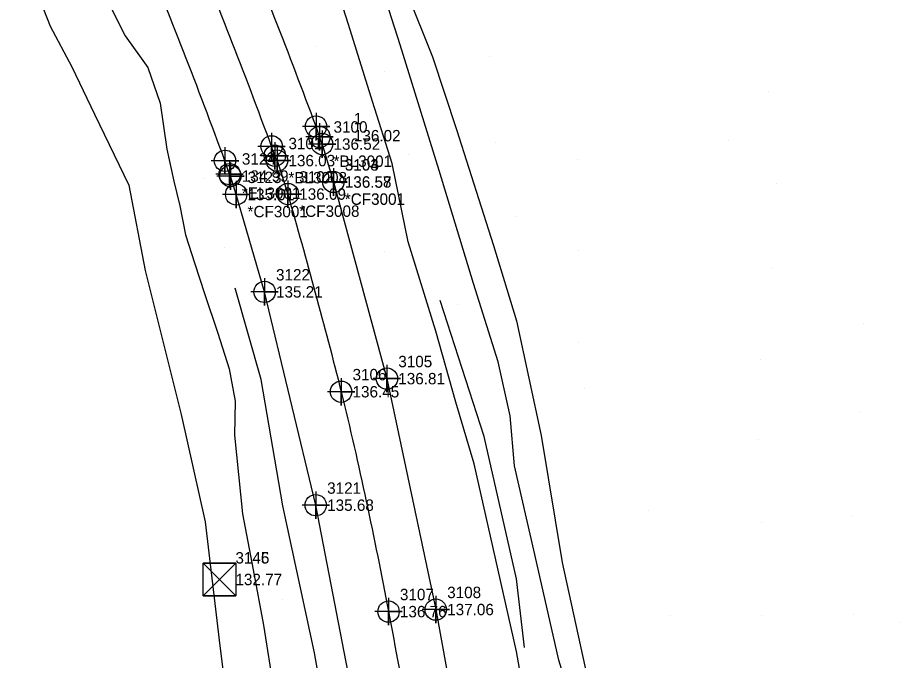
# Model space of a CAD drawing. Extents: x 2312183 to 2312663, y 819676 to 820746.
# Drawn here: x 2312371.9 to 2312565.2, y 820324.9 to 820465.8 of the extents above; entities that cross this region are included whole.
import ezdxf

# ---------------------------------------------------------------- set-up
doc = ezdxf.new("R2010")
doc.units = 0
for name, color, linetype in [('CTL Bench Mark CELL', 7, 'Continuous'), ('CTL Bench Mark Cogo Elevation', 7, 'Continuous'), ('CTL Bench Mark Cogo Number', 7, 'Continuous'), ('CTL Supplemental Horizontal and Vertical Cogo Elevation', 7, 'Continuous'), ('CTL Supplemental Horizontal and Vertical Cogo Number', 7, 'Continuous'), ('Exist DTM Crownline', 7, 'Continuous'), ('Exist DTM Crownline Cogo Comment', 7, 'Continuous'), ('Exist DTM Crownline Cogo Elevation', 7, 'Continuous'), ('Exist DTM Crownline Cogo Number', 7, 'Continuous'), ('Exist DTM Crownline Cogo Point CELL', 7, 'Continuous'), ('Exist Roads EOP', 7, 'Continuous'), ('Exist Roads EOP Cogo Comment', 7, 'Continuous'), ('Exist Roads EOP Cogo Elevation', 7, 'Continuous'), ('Exist Roads EOP Cogo Number', 7, 'Continuous'), ('Exist Roads EOP Cogo Point CELL', 7, 'Continuous'), ('PH Exist DTM Breakline', 7, 'Continuous'), ('PH Exist DTM Point', 7, 'Continuous')]:
    doc.layers.add(name, color=color, linetype=linetype)

msp = doc.modelspace()

# ---------------------------------------------------------------- linework, layer by layer
at = {"layer": 'CTL Bench Mark CELL'}
msp.add_line((2312416.1, 820342.6), (2312416.1, 820342.6), dxfattribs=at)
msp.add_line((2312416.1, 820342.6), (2312416.1, 820342.6), dxfattribs=at)
msp.add_line((2312416.1, 820342.6), (2312416.1, 820342.6), dxfattribs=at)
msp.add_line((2312416.1, 820342.6), (2312416.1, 820342.6), dxfattribs=at)
msp.add_lwpolyline([(2312412.5, 820346.19), (2312419.69, 820346.19), (2312419.69, 820339), (2312412.5, 820339)], close=True, dxfattribs=at)
msp.add_lwpolyline([(2312412.5, 820346.19), (2312419.69, 820346.19), (2312419.69, 820339), (2312412.5, 820339)], close=True, dxfattribs=at)
msp.add_lwpolyline([(2312412.5, 820346.19), (2312419.69, 820346.19), (2312419.69, 820339), (2312412.5, 820339)], close=True, dxfattribs=at)
msp.add_lwpolyline([(2312412.5, 820346.19), (2312419.69, 820346.19), (2312419.69, 820339), (2312412.5, 820339)], close=True, dxfattribs=at)
for points in [[(2312419.69, 820346.19), (2312412.5, 820339), (2312416.1, 820342.6), (2312419.69, 820339), (2312412.5, 820346.19)], [(2312416.1, 820342.6), (2312419.69, 820346.19), (2312412.5, 820346.19), (2312416.1, 820342.6)], [(2312419.69, 820346.19), (2312412.5, 820339), (2312416.1, 820342.59), (2312419.69, 820339), (2312412.5, 820346.19)], [(2312416.1, 820342.59), (2312419.69, 820346.19), (2312412.5, 820346.19), (2312416.1, 820342.59)], [(2312419.69, 820346.19), (2312412.5, 820339), (2312416.1, 820342.59), (2312419.69, 820339), (2312412.5, 820346.19)], [(2312416.1, 820342.59), (2312419.69, 820346.19), (2312412.5, 820346.19), (2312416.1, 820342.59)], [(2312419.69, 820346.19), (2312412.5, 820339), (2312416.1, 820342.6), (2312419.69, 820339), (2312412.5, 820346.19)], [(2312416.1, 820342.6), (2312419.69, 820346.19), (2312412.5, 820346.19), (2312416.1, 820342.6)], [(2312416.1, 820342.6), (2312412.5, 820339), (2312419.69, 820339), (2312416.1, 820342.6)], [(2312416.1, 820342.6), (2312412.5, 820339), (2312419.69, 820339), (2312416.1, 820342.6)], [(2312416.1, 820342.59), (2312412.5, 820339), (2312419.69, 820339), (2312416.1, 820342.59)], [(2312416.1, 820342.59), (2312412.5, 820339), (2312419.69, 820339), (2312416.1, 820342.59)]]:
    msp.add_lwpolyline(points, dxfattribs=at)
at = {"layer": 'Exist DTM Crownline'}
for p, q in [((2312428.23, 820435.5), (2312427.52, 820437.54)), ((2312428.71, 820434.43), (2312431.08, 820427.09))]:
    msp.add_line(p, q, dxfattribs=at)
msp.add_lwpolyline([(2312428.71, 820434.43), (2312428.23, 820435.5)], dxfattribs=at)
for points in [[(2312427.52, 820437.54), (2312408.57, 820485.39), (2312385.43, 820531.09), (2312358.13, 820575.86), (2312333.19, 820609.81), (2312297.49, 820652.78)], [(2312431.08, 820427.09), (2312442.75, 820383.76), (2312453.13, 820335.56), (2312461.58, 820287.26), (2312468.33, 820241.58), (2312470.08, 820228.19)]]:
    msp.add_spline(points, degree=3, dxfattribs=at)
at = {"layer": 'Exist DTM Crownline Cogo Point CELL'}
for points in [[(2312427.52, 820440.54), (2312427.52, 820434.54), (2312427.52, 820437.54), (2312430.52, 820437.54), (2312424.52, 820437.54)], [(2312428.23, 820438.5), (2312428.23, 820432.5), (2312428.23, 820435.5), (2312431.23, 820435.5), (2312425.23, 820435.5)], [(2312428.71, 820437.43), (2312428.71, 820431.43), (2312428.71, 820434.43), (2312431.71, 820434.43), (2312425.71, 820434.43)], [(2312428.71, 820437.43), (2312428.71, 820431.43), (2312428.71, 820434.43), (2312431.71, 820434.43), (2312425.71, 820434.43)], [(2312431.08, 820430.09), (2312431.08, 820424.09), (2312431.08, 820427.09), (2312434.08, 820427.09), (2312428.08, 820427.09)], [(2312431.08, 820430.09), (2312431.08, 820424.09), (2312431.08, 820427.09), (2312434.08, 820427.09), (2312428.08, 820427.09)], [(2312442.75, 820386.76), (2312442.75, 820380.76), (2312442.75, 820383.76), (2312445.75, 820383.76), (2312439.75, 820383.76)], [(2312442.75, 820386.76), (2312442.75, 820380.76), (2312442.75, 820383.76), (2312445.75, 820383.76), (2312439.75, 820383.76)], [(2312453.13, 820338.56), (2312453.13, 820332.56), (2312453.13, 820335.56), (2312456.13, 820335.56), (2312450.13, 820335.56)], [(2312453.13, 820338.56), (2312453.13, 820332.56), (2312453.13, 820335.56), (2312456.13, 820335.56), (2312450.13, 820335.56)]]:
    msp.add_lwpolyline(points, dxfattribs=at)
for centre in [(2312427.52, 820437.54), (2312428.23, 820435.5), (2312428.71, 820434.43), (2312428.71, 820434.43), (2312431.08, 820427.09), (2312431.08, 820427.09), (2312442.75, 820383.76), (2312442.75, 820383.76), (2312453.13, 820335.56), (2312453.13, 820335.56)]:
    msp.add_circle(centre, 2.34, dxfattribs=at)
at = {"layer": 'Exist Roads EOP'}
for p, q in [((2312438.01, 820439.61), (2312437.27, 820441.9)), ((2312438.59, 820438.05), (2312441.06, 820429.72)), ((2312418.31, 820431.45), (2312417.31, 820434.38)), ((2312419.76, 820427), (2312418.51, 820431.04)), ((2312441.06, 820429.72), (2312441.05, 820429.75))]:
    msp.add_line(p, q, dxfattribs=at)
for points in [[(2312438.59, 820438.05), (2312438.01, 820439.61)], [(2312418.51, 820431.04), (2312418.31, 820431.45)], [(2312441.05, 820429.75), (2312452.77, 820386.63), (2312463.48, 820336.01), (2312472.02, 820288.73), (2312479.07, 820242.19), (2312480.59, 820230.27)], [(2312459.22, 820221.98), (2312453.84, 820264.93), (2312446.37, 820311.63), (2312437.19, 820358.89), (2312425.99, 820405.65), (2312419.76, 820427)]]:
    msp.add_lwpolyline(points, dxfattribs=at)
for points in [[(2312437.27, 820441.9), (2312418.59, 820489.03), (2312394.67, 820536.19), (2312367.38, 820580.54)], [(2312417.31, 820434.38), (2312398.47, 820481.99), (2312376.08, 820525.96), (2312349.36, 820569.45)]]:
    msp.add_spline(points, degree=3, dxfattribs=at)
at = {"layer": 'Exist Roads EOP Cogo Point CELL'}
for points in [[(2312437.27, 820444.9), (2312437.27, 820438.9), (2312437.27, 820441.9), (2312440.27, 820441.9), (2312434.27, 820441.9)], [(2312438.01, 820442.61), (2312438.01, 820436.61), (2312438.01, 820439.61), (2312441.01, 820439.61), (2312435.01, 820439.61)], [(2312438.59, 820441.05), (2312438.59, 820435.05), (2312438.59, 820438.05), (2312441.59, 820438.05), (2312435.59, 820438.05)], [(2312438.59, 820441.05), (2312438.59, 820435.05), (2312438.59, 820438.05), (2312441.59, 820438.05), (2312435.59, 820438.05)], [(2312438.59, 820441.05), (2312438.59, 820435.05), (2312438.59, 820438.05), (2312441.59, 820438.05), (2312435.59, 820438.05)], [(2312417.31, 820437.38), (2312417.31, 820431.38), (2312417.31, 820434.38), (2312420.31, 820434.38), (2312414.31, 820434.38)], [(2312418.31, 820434.45), (2312418.31, 820428.45), (2312418.31, 820431.45), (2312421.31, 820431.45), (2312415.31, 820431.45)], [(2312418.51, 820434.04), (2312418.51, 820428.04), (2312418.51, 820431.04), (2312421.51, 820431.04), (2312415.51, 820431.04)], [(2312418.51, 820434.04), (2312418.51, 820428.04), (2312418.51, 820431.04), (2312421.51, 820431.04), (2312415.51, 820431.04)], [(2312418.51, 820434.04), (2312418.51, 820428.04), (2312418.51, 820431.04), (2312421.51, 820431.04), (2312415.51, 820431.04)], [(2312441.05, 820432.75), (2312441.05, 820426.75), (2312441.05, 820429.75), (2312444.05, 820429.75), (2312438.05, 820429.75)], [(2312441.05, 820432.75), (2312441.05, 820426.75), (2312441.05, 820429.75), (2312444.05, 820429.75), (2312438.05, 820429.75)], [(2312441.05, 820432.75), (2312441.05, 820426.75), (2312441.05, 820429.75), (2312444.05, 820429.75), (2312438.05, 820429.75)], [(2312441.06, 820432.72), (2312441.06, 820426.72), (2312441.06, 820429.72), (2312444.06, 820429.72), (2312438.06, 820429.72)], [(2312441.06, 820432.72), (2312441.06, 820426.72), (2312441.06, 820429.72), (2312444.06, 820429.72), (2312438.06, 820429.72)], [(2312441.06, 820432.72), (2312441.06, 820426.72), (2312441.06, 820429.72), (2312444.06, 820429.72), (2312438.06, 820429.72)], [(2312419.76, 820430), (2312419.76, 820424), (2312419.76, 820427), (2312422.76, 820427), (2312416.76, 820427)], [(2312419.76, 820430), (2312419.76, 820424), (2312419.76, 820427), (2312422.76, 820427), (2312416.76, 820427)], [(2312419.76, 820430), (2312419.76, 820424), (2312419.76, 820427), (2312422.76, 820427), (2312416.76, 820427)], [(2312425.99, 820408.65), (2312425.99, 820402.65), (2312425.99, 820405.65), (2312428.99, 820405.65), (2312422.99, 820405.65)], [(2312425.99, 820408.65), (2312425.99, 820402.65), (2312425.99, 820405.65), (2312428.99, 820405.65), (2312422.99, 820405.65)], [(2312425.99, 820408.65), (2312425.99, 820402.65), (2312425.99, 820405.65), (2312428.99, 820405.65), (2312422.99, 820405.65)], [(2312452.77, 820389.63), (2312452.77, 820383.63), (2312452.77, 820386.63), (2312455.77, 820386.63), (2312449.77, 820386.63)], [(2312452.77, 820389.63), (2312452.77, 820383.63), (2312452.77, 820386.63), (2312455.77, 820386.63), (2312449.77, 820386.63)], [(2312437.19, 820361.89), (2312437.19, 820355.89), (2312437.19, 820358.89), (2312440.19, 820358.89), (2312434.19, 820358.89)], [(2312437.19, 820361.89), (2312437.19, 820355.89), (2312437.19, 820358.89), (2312440.19, 820358.89), (2312434.19, 820358.89)], [(2312437.19, 820361.89), (2312437.19, 820355.89), (2312437.19, 820358.89), (2312440.19, 820358.89), (2312434.19, 820358.89)], [(2312463.48, 820339.01), (2312463.48, 820333.01), (2312463.48, 820336.01), (2312466.48, 820336.01), (2312460.48, 820336.01)], [(2312463.48, 820339.01), (2312463.48, 820333.01), (2312463.48, 820336.01), (2312466.48, 820336.01), (2312460.48, 820336.01)], [(2312463.48, 820339.01), (2312463.48, 820333.01), (2312463.48, 820336.01), (2312466.48, 820336.01), (2312460.48, 820336.01)]]:
    msp.add_lwpolyline(points, dxfattribs=at)
for centre in [(2312437.27, 820441.9), (2312438.01, 820439.61), (2312438.59, 820438.05), (2312438.59, 820438.05), (2312438.59, 820438.05), (2312417.31, 820434.38), (2312418.31, 820431.45), (2312418.51, 820431.04), (2312418.51, 820431.04), (2312418.51, 820431.04), (2312441.05, 820429.75), (2312441.05, 820429.75), (2312441.05, 820429.75), (2312441.06, 820429.72), (2312441.06, 820429.72), (2312441.06, 820429.72), (2312419.76, 820427), (2312419.76, 820427), (2312419.76, 820427), (2312425.99, 820405.65), (2312425.99, 820405.65), (2312425.99, 820405.65), (2312452.77, 820386.63), (2312452.77, 820386.63), (2312437.19, 820358.89), (2312437.19, 820358.89), (2312437.19, 820358.89), (2312463.48, 820336.01), (2312463.48, 820336.01), (2312463.48, 820336.01)]:
    msp.add_circle(centre, 2.34, dxfattribs=at)
at = {"layer": 'PH Exist DTM Breakline'}
for points in [[(2312477.16, 820390.3), (2312471.74, 820407.46), (2312464.23, 820432.23), (2312455.71, 820459.83), (2312449.64, 820478.79), (2312444.49, 820489.71), (2312438.95, 820498.67), (2312430.86, 820508.29), (2312423.23, 820518.79), (2312417.85, 820527.39), (2312410.24, 820542.77), (2312403.93, 820554.09), (2312394.96, 820567.28), (2312386.75, 820580.38), (2312374.65, 820596.09)], [(2312496.98, 820211.89), (2312494.87, 820230.31), (2312493.52, 820258.27), (2312489.57, 820280.07), (2312484.22, 820309.45), (2312481.15, 820326.81), (2312475.44, 820352.08), (2312471.91, 820367.92), (2312467.91, 820381.46), (2312463.46, 820397.01), (2312457.42, 820416.6), (2312453.92, 820433.79), (2312449.6, 820447.37), (2312444.37, 820464.27), (2312438.97, 820481.2), (2312434.26, 820489.97), (2312425.05, 820503.84), (2312418.26, 820512.36), (2312411.06, 820524.77), (2312404.5, 820537.31), (2312396.07, 820550.91), (2312386.97, 820563.26), (2312378.04, 820577.42), (2312367.52, 820592.37)], [(2312323.19, 820565.09), (2312341.16, 820534.9), (2312360.25, 820506.1), (2312372.41, 820480.89), (2312379, 820463.92), (2312383.77, 820454.95), (2312388.75, 820444.62), (2312396.25, 820429.05), (2312399.86, 820410.35), (2312407.68, 820378.77), (2312412.99, 820355.24), (2312416.17, 820328.02), (2312417.67, 820316.52), (2312422.05, 820275.27)], [(2312391.16, 820470.38), (2312395.48, 820461.78), (2312400.38, 820454.86), (2312403.14, 820447.03), (2312404.56, 820436.92), (2312406.09, 820429.89), (2312407.4, 820424.49), (2312408.69, 820418.16), (2312410.67, 820411.79), (2312412.86, 820405.28), (2312415.75, 820396.58), (2312418.23, 820388.76), (2312419.52, 820381.7), (2312419.42, 820374.21), (2312421.17, 820356.99), (2312423.46, 820344.75), (2312425.78, 820332.58), (2312428.01, 820318.28), (2312429.7, 820304.94), (2312430.08, 820283.91), (2312430.55, 820272.02), (2312432.01, 820256.8), (2312435.53, 820209.02), (2312436.94, 820204.43)], [(2312457.31, 820470.89), (2312462.78, 820457.19), (2312468.03, 820441.23), (2312476.14, 820415.82), (2312481.16, 820399.28), (2312486.57, 820374.14), (2312491.18, 820346.35), (2312497.16, 820318.89), (2312506.05, 820290.48), (2312509.86, 820279.25), (2312517.03, 820263.97), (2312521.4, 820250.94), (2312524.81, 820240.42), (2312528.04, 820230.48), (2312531.48, 820219.81)], [(2312455.99, 820200.73), (2312449.75, 820231.37), (2312446.75, 820268.11), (2312440.9, 820303.62), (2312436.92, 820326.5), (2312429.99, 820358.74), (2312425.22, 820386.43), (2312419.51, 820406.46)], [(2312482.95, 820327.66), (2312481.14, 820342.74), (2312474.11, 820373.94), (2312464.42, 820403.76)], [(2312502.61, 820280.69), (2312499.1, 820296.81), (2312490.43, 820324.88), (2312485.21, 820348.1), (2312480.72, 820367.48), (2312479.81, 820378.49), (2312477.16, 820390.3)]]:
    msp.add_lwpolyline(points, dxfattribs=at)
at = {"layer": 'PH Exist DTM Point'}
for p, q in [((2312437.25, 820459.49), (2312437.25, 820459.49)), ((2312475.19, 820457.14), (2312475.19, 820457.14)), ((2312452.19, 820453.89), (2312452.19, 820453.89)), ((2312536.4, 820449.58), (2312536.4, 820449.58)), ((2312527.64, 820438.76), (2312527.64, 820438.76)), ((2312476.61, 820438.32), (2312476.61, 820438.32)), ((2312457.47, 820435.71), (2312457.47, 820435.71)), ((2312494.63, 820434.61), (2312494.63, 820434.61)), ((2312412.64, 820430.61), (2312412.64, 820430.61)), ((2312538.09, 820429.49), (2312538.09, 820429.49)), ((2312481.27, 820422.12), (2312481.27, 820422.12)), ((2312417.2, 820415.35), (2312417.2, 820415.35)), ((2312452.32, 820414.58), (2312452.32, 820414.58)), ((2312494.79, 820414.66), (2312494.79, 820414.66)), ((2312537.34, 820410.69), (2312537.34, 820410.69)), ((2312468.25, 820402.81), (2312468.25, 820402.81)), ((2312557.21, 820398.72), (2312557.21, 820398.72)), ((2312494.69, 820394.63), (2312494.69, 820394.63)), ((2312534.52, 820390.76), (2312534.52, 820390.76)), ((2312496.03, 820384.45), (2312496.03, 820384.45)), ((2312556.61, 820379.12), (2312556.61, 820379.12)), ((2312534.27, 820373.25), (2312534.27, 820373.25)), ((2312510.05, 820357.63), (2312510.05, 820357.63)), ((2312554.56, 820356.36), (2312554.56, 820356.36)), ((2312534.72, 820355.14), (2312534.72, 820355.14)), ((2312429.98, 820338.25), (2312429.98, 820338.25)), ((2312474.46, 820335.27), (2312474.46, 820335.27)), ((2312514.87, 820334.69), (2312514.87, 820334.69)), ((2312534.77, 820334.66), (2312534.77, 820334.66)), ((2312555.08, 820334.85), (2312555.08, 820334.85)), ((2312565.24, 820333.17), (2312565.24, 820333.17))]:
    msp.add_line(p, q, dxfattribs=at)

# ---------------------------------------------------------------- texts
at = {"layer": 'CTL Bench Mark Cogo Elevation'}
msp.add_text('132.77', height=2.5, dxfattribs=at).set_placement((2312419.6, 820341.35))
msp.add_text('132.77', height=2.5, dxfattribs=at).set_placement((2312419.6, 820341.35))
at = {"layer": 'CTL Bench Mark Cogo Number'}
for s in ['3145', '3146']:
    msp.add_text(s, height=2.5, dxfattribs=at).set_placement((2312419.6, 820346.1))
at = {"layer": 'CTL Supplemental Horizontal and Vertical Cogo Elevation'}
msp.add_text('136.02', height=2.5, dxfattribs=at).set_placement((2312445.55, 820438.64))
at = {"layer": 'CTL Supplemental Horizontal and Vertical Cogo Number'}
msp.add_text('1', height=2.5, dxfattribs=at).set_placement((2312445.55, 820442.39))
at = {"layer": 'Exist DTM Crownline Cogo Comment'}
for s, p in [('*BL3008', (2312431.21, 820429.43)), ('*CF3008', (2312433.58, 820422.09))]:
    msp.add_text(s, height=2.5, dxfattribs=at).set_placement(p)
at = {"layer": 'Exist DTM Crownline Cogo Elevation'}
for s, p in [('136.03', (2312431.21, 820433.18)), ('136.09', (2312433.58, 820425.84)), ('136.45', (2312445.25, 820382.51)), ('136.76', (2312455.63, 820334.31))]:
    msp.add_text(s, height=2.5, dxfattribs=at).set_placement(p)
at = {"layer": 'Exist DTM Crownline Cogo Number'}
for s, p in [('3101', (2312431.21, 820436.93)), ('3102', (2312433.58, 820429.59)), ('3106', (2312445.25, 820386.26)), ('3107', (2312455.63, 820338.06))]:
    msp.add_text(s, height=2.5, dxfattribs=at).set_placement(p)
at = {"layer": 'Exist Roads EOP Cogo Comment'}
for s, p in [('*BL3001', (2312441.09, 820433.05)), ('*EL3001', (2312421.01, 820426.04)), ('*CF3001', (2312443.55, 820424.75)), ('*CF3001', (2312443.56, 820424.72)), ('*CF3001', (2312422.26, 820422))]:
    msp.add_text(s, height=2.5, dxfattribs=at).set_placement(p)
at = {"layer": 'Exist Roads EOP Cogo Elevation'}
for s, p in [('136.52', (2312441.09, 820436.8)), ('134.99', (2312421.01, 820429.79)), ('136.58', (2312443.55, 820428.5)), ('136.57', (2312443.56, 820428.47)), ('135.01', (2312422.26, 820425.75)), ('135.21', (2312428.49, 820404.4)), ('136.81', (2312455.27, 820385.38)), ('135.68', (2312439.69, 820357.64)), ('137.06', (2312465.98, 820334.76))]:
    msp.add_text(s, height=2.5, dxfattribs=at).set_placement(p)
at = {"layer": 'Exist Roads EOP Cogo Number'}
for s, p in [('3100', (2312441.09, 820440.55)), ('3124', (2312421.01, 820433.54)), ('3104', (2312443.55, 820432.25)), ('3103', (2312443.56, 820432.22)), ('3123', (2312422.26, 820429.5)), ('3122', (2312428.49, 820408.15)), ('3105', (2312455.27, 820389.13)), ('3121', (2312439.69, 820361.39)), ('3108', (2312465.98, 820338.51))]:
    msp.add_text(s, height=2.5, dxfattribs=at).set_placement(p)

doc.saveas('drawing.dxf')
